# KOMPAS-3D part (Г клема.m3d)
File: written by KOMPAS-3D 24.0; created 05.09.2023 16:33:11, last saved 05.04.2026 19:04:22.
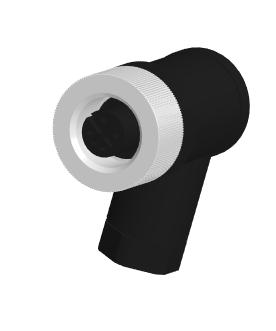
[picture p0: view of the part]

Document properties: Полное имя файла: E:\Работа\Зайцев\Аксессуары для пневмоприводов\Электропневматические позиционеры DN.ru\ЭИП Электропневматический позиционер DN.ru\ЭИП-1500 Электропневматический позиционер DN.ru\3D модели. Позиционер VALMA LPOS-S-V1 (КОМПАС)\Г клема.m3d

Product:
- Body: Тело 15  | qty 1
    Масса: 0.000295
- Body: Тело 14  | qty 1
    Масса: 0.014096
- Body: Тело 13  | qty 1
    Масса: 0.056783

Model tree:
1. Операция без истории:13
2. Операция без истории:14
3. Операция без истории:15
